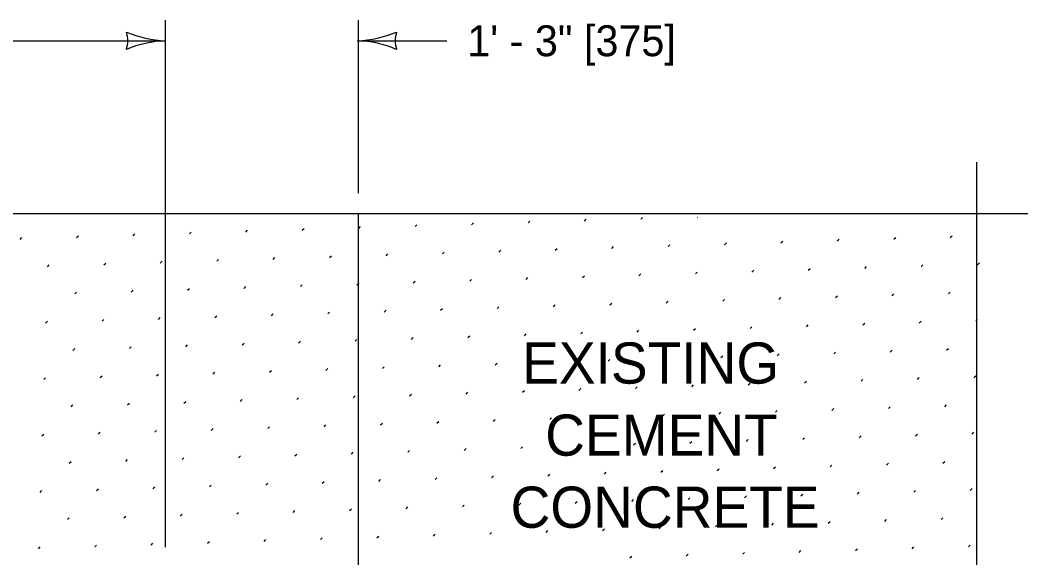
# Model space of a CAD drawing. Extents: x 49991.4 to 50021, y 49987.6 to 50011.4.
# Drawn here: x 50005.45 to 50007.407, y 49992.135 to 49993.18 of the extents above; entities that cross this region are included whole.
import ezdxf

# ---------------------------------------------------------------- set-up
doc = ezdxf.new("R2010")
doc.units = 0
for name, color, linetype in [('Level 1', 7, 'Continuous'), ('Level 10', 7, 'Continuous'), ('Level 2', 7, 'Continuous'), ('Level 3', 7, 'Continuous'), ('Level 6', 7, 'Continuous')]:
    doc.layers.add(name, color=color, linetype=linetype)

msp = doc.modelspace()

# ---------------------------------------------------------------- linework, layer by layer
at = {"layer": 'Level 1'}
msp.add_line((50006.1071, 49991.8039), (50006.1071, 49992.8039), dxfattribs=at)
at = {"layer": 'Level 10'}
for p, q in [((50006.4361, 49992.786), (50006.4396, 49992.7896)), ((50006.5457, 49992.7896), (50006.5492, 49992.7931)), ((50006.6553, 49992.7931), (50006.6588, 49992.7967)), ((50006.7649, 49992.7967), (50006.7656, 49992.7974)), ((50005.7784, 49992.7648), (50005.7819, 49992.7683)), ((50005.888, 49992.7683), (50005.8915, 49992.7719)), ((50005.9976, 49992.7719), (50006.0012, 49992.7754)), ((50006.1072, 49992.7754), (50006.1108, 49992.779)), ((50006.2168, 49992.779), (50006.2204, 49992.7825)), ((50006.3264, 49992.7825), (50006.33, 49992.786)), ((50005.4496, 49992.7542), (50005.4531, 49992.7577)), ((50005.5592, 49992.7577), (50005.5627, 49992.7612)), ((50005.6688, 49992.7612), (50005.6723, 49992.7648)), ((50006.9275, 49992.7472), (50006.9311, 49992.7507)), ((50007.0371, 49992.7507), (50007.0407, 49992.7543)), ((50007.1467, 49992.7543), (50007.1503, 49992.7578)), ((50007.2563, 49992.7578), (50007.2599, 49992.7613)), ((50006.2699, 49992.7259), (50006.2734, 49992.7295)), ((50006.3795, 49992.7295), (50006.383, 49992.733)), ((50006.4891, 49992.733), (50006.4926, 49992.7366)), ((50006.5987, 49992.7366), (50006.6022, 49992.7401)), ((50006.7083, 49992.7401), (50006.7118, 49992.7436)), ((50006.8179, 49992.7436), (50006.8214, 49992.7472)), ((50005.7218, 49992.7082), (50005.7254, 49992.7118)), ((50005.8314, 49992.7118), (50005.835, 49992.7153)), ((50005.941, 49992.7153), (50005.9446, 49992.7188)), ((50006.0507, 49992.7188), (50006.0542, 49992.7224)), ((50006.1603, 49992.7224), (50006.1638, 49992.7259)), ((50005.5026, 49992.7011), (50005.5061, 49992.7047)), ((50005.6122, 49992.7047), (50005.6158, 49992.7082)), ((50006.7613, 49992.6871), (50006.7649, 49992.6906)), ((50006.8709, 49992.6906), (50006.8745, 49992.6941)), ((50006.9806, 49992.6942), (50006.9841, 49992.6977)), ((50007.0902, 49992.6977), (50007.0937, 49992.7012)), ((50007.1998, 49992.7012), (50007.2033, 49992.7048)), ((50007.3094, 49992.7048), (50007.3129, 49992.7083)), ((50006.1037, 49992.6658), (50006.1072, 49992.6693)), ((50006.2133, 49992.6694), (50006.2168, 49992.6729)), ((50006.3229, 49992.6729), (50006.3264, 49992.6764)), ((50006.4325, 49992.6764), (50006.436, 49992.68)), ((50006.5421, 49992.68), (50006.5457, 49992.6835)), ((50006.6517, 49992.6835), (50006.6553, 49992.6871)), ((50005.5556, 49992.6481), (50005.5592, 49992.6516)), ((50005.6652, 49992.6516), (50005.6688, 49992.6552)), ((50005.7749, 49992.6552), (50005.7784, 49992.6587)), ((50005.8845, 49992.6587), (50005.888, 49992.6623)), ((50005.9941, 49992.6623), (50005.9976, 49992.6658)), ((50007.2528, 49992.6482), (50007.2563, 49992.6517)), ((50006.5952, 49992.6269), (50006.5987, 49992.6305)), ((50006.7048, 49992.6305), (50006.7083, 49992.634)), ((50006.8144, 49992.634), (50006.8179, 49992.6376)), ((50006.924, 49992.6376), (50006.9275, 49992.6411)), ((50007.0336, 49992.6411), (50007.0371, 49992.6447)), ((50007.1432, 49992.6447), (50007.1467, 49992.6482)), ((50006.0471, 49992.6092), (50006.0506, 49992.6128)), ((50006.1567, 49992.6128), (50006.1603, 49992.6163)), ((50006.2663, 49992.6163), (50006.2699, 49992.6199)), ((50006.3759, 49992.6199), (50006.3795, 49992.6234)), ((50006.4855, 49992.6234), (50006.4891, 49992.6269)), ((50005.4991, 49992.5915), (50005.5026, 49992.5951)), ((50005.6087, 49992.5951), (50005.6122, 49992.5986)), ((50005.7183, 49992.5986), (50005.7218, 49992.6021)), ((50005.8279, 49992.6022), (50005.8314, 49992.6057)), ((50005.9375, 49992.6057), (50005.941, 49992.6092)), ((50007.0866, 49992.5881), (50007.0902, 49992.5916)), ((50007.1962, 49992.5916), (50007.1998, 49992.5952)), ((50007.3058, 49992.5952), (50007.3094, 49992.5987)), ((50006.5386, 49992.5704), (50006.5421, 49992.5739)), ((50006.6482, 49992.5739), (50006.6517, 49992.5775)), ((50006.7578, 49992.5775), (50006.7613, 49992.581)), ((50006.8674, 49992.581), (50006.8709, 49992.5845)), ((50006.977, 49992.5845), (50006.9805, 49992.5881)), ((50005.8809, 49992.5491), (50005.8845, 49992.5527)), ((50005.9905, 49992.5527), (50005.9941, 49992.5562)), ((50006.1001, 49992.5562), (50006.1037, 49992.5597)), ((50006.2097, 49992.5597), (50006.2133, 49992.5633)), ((50006.3194, 49992.5633), (50006.3229, 49992.5668)), ((50006.429, 49992.5668), (50006.4325, 49992.5704)), ((50005.5521, 49992.5385), (50005.5556, 49992.542)), ((50005.6617, 49992.542), (50005.6652, 49992.5456)), ((50005.7713, 49992.5456), (50005.7749, 49992.5491)), ((50007.03, 49992.5315), (50007.0336, 49992.535)), ((50007.1397, 49992.5351), (50007.1432, 49992.5386)), ((50007.2493, 49992.5386), (50007.2528, 49992.5421)), ((50006.3724, 49992.5103), (50006.3759, 49992.5138)), ((50006.482, 49992.5138), (50006.4855, 49992.5173)), ((50006.5916, 49992.5173), (50006.5951, 49992.5209)), ((50006.7012, 49992.5209), (50006.7048, 49992.5244)), ((50006.8108, 49992.5244), (50006.8144, 49992.528)), ((50006.9204, 49992.528), (50006.924, 49992.5315)), ((50005.8243, 49992.4925), (50005.8279, 49992.4961)), ((50005.934, 49992.4961), (50005.9375, 49992.4996)), ((50006.0436, 49992.4996), (50006.0471, 49992.5032)), ((50006.1532, 49992.5032), (50006.1567, 49992.5067)), ((50006.2628, 49992.5067), (50006.2663, 49992.5102)), ((50005.4955, 49992.4819), (50005.4991, 49992.4854)), ((50005.6051, 49992.4855), (50005.6087, 49992.489)), ((50005.7147, 49992.489), (50005.7183, 49992.4925)), ((50006.8639, 49992.4714), (50006.8674, 49992.4749)), ((50006.9735, 49992.4749), (50006.977, 49992.4785)), ((50007.0831, 49992.4785), (50007.0866, 49992.482)), ((50007.1927, 49992.482), (50007.1962, 49992.4856)), ((50007.3023, 49992.4856), (50007.3058, 49992.4891)), ((50006.3158, 49992.4537), (50006.3194, 49992.4572)), ((50006.4254, 49992.4572), (50006.429, 49992.4608)), ((50006.535, 49992.4608), (50006.5386, 49992.4643)), ((50006.6446, 49992.4643), (50006.6482, 49992.4678)), ((50006.7543, 49992.4678), (50006.7578, 49992.4714)), ((50005.6582, 49992.4324), (50005.6617, 49992.436)), ((50005.7678, 49992.436), (50005.7713, 49992.4395)), ((50005.8774, 49992.4395), (50005.8809, 49992.443)), ((50005.987, 49992.4431), (50005.9905, 49992.4466)), ((50006.0966, 49992.4466), (50006.1001, 49992.4501)), ((50006.2062, 49992.4501), (50006.2097, 49992.4537)), ((50005.5486, 49992.4289), (50005.5521, 49992.4324)), ((50006.8073, 49992.4148), (50006.8108, 49992.4184)), ((50006.9169, 49992.4184), (50006.9204, 49992.4219)), ((50007.0265, 49992.4219), (50007.03, 49992.4254)), ((50007.1361, 49992.4254), (50007.1396, 49992.429)), ((50007.2457, 49992.429), (50007.2493, 49992.4325)), ((50006.1496, 49992.3936), (50006.1532, 49992.3971)), ((50006.2592, 49992.3971), (50006.2628, 49992.4006)), ((50006.3688, 49992.4006), (50006.3724, 49992.4042)), ((50006.4785, 49992.4042), (50006.482, 49992.4077)), ((50006.5881, 49992.4077), (50006.5916, 49992.4113)), ((50006.6977, 49992.4113), (50006.7012, 49992.4148)), ((50005.492, 49992.3723), (50005.4955, 49992.3758)), ((50005.6016, 49992.3758), (50005.6051, 49992.3794)), ((50005.7112, 49992.3794), (50005.7147, 49992.3829)), ((50005.8208, 49992.3829), (50005.8243, 49992.3865)), ((50005.9304, 49992.3865), (50005.9339, 49992.39)), ((50006.04, 49992.39), (50006.0436, 49992.3936)), ((50007.1891, 49992.3724), (50007.1927, 49992.3759)), ((50007.2988, 49992.376), (50007.3023, 49992.3795)), ((50006.6411, 49992.3547), (50006.6446, 49992.3582)), ((50006.7507, 49992.3582), (50006.7542, 49992.3618)), ((50006.8603, 49992.3618), (50006.8639, 49992.3653)), ((50006.9699, 49992.3653), (50006.9735, 49992.3689)), ((50007.0795, 49992.3689), (50007.0831, 49992.3724)), ((50005.9834, 49992.3334), (50005.987, 49992.337)), ((50006.0931, 49992.337), (50006.0966, 49992.3405)), ((50006.2027, 49992.3405), (50006.2062, 49992.3441)), ((50006.3123, 49992.3441), (50006.3158, 49992.3476)), ((50006.4219, 49992.3476), (50006.4254, 49992.3511)), ((50006.5315, 49992.3512), (50006.535, 49992.3547)), ((50005.545, 49992.3193), (50005.5485, 49992.3228)), ((50005.6546, 49992.3228), (50005.6582, 49992.3264)), ((50005.7642, 49992.3264), (50005.7678, 49992.3299)), ((50005.8738, 49992.3299), (50005.8774, 49992.3334)), ((50007.1326, 49992.3158), (50007.1361, 49992.3194)), ((50007.2422, 49992.3194), (50007.2457, 49992.3229)), ((50006.4749, 49992.2946), (50006.4785, 49992.2981)), ((50006.5845, 49992.2981), (50006.5881, 49992.3017)), ((50006.6941, 49992.3017), (50006.6977, 49992.3052)), ((50006.8037, 49992.3052), (50006.8073, 49992.3087)), ((50006.9133, 49992.3088), (50006.9169, 49992.3123)), ((50007.023, 49992.3123), (50007.0265, 49992.3158)), ((50005.9269, 49992.2769), (50005.9304, 49992.2804)), ((50006.0365, 49992.2804), (50006.04, 49992.2839)), ((50006.1461, 49992.284), (50006.1496, 49992.2875)), ((50006.2557, 49992.2875), (50006.2592, 49992.291)), ((50006.3653, 49992.291), (50006.3688, 49992.2946)), ((50005.4884, 49992.2627), (50005.492, 49992.2662)), ((50005.598, 49992.2662), (50005.6016, 49992.2698)), ((50005.7077, 49992.2698), (50005.7112, 49992.2733)), ((50005.8173, 49992.2733), (50005.8208, 49992.2769)), ((50006.9664, 49992.2557), (50006.9699, 49992.2593)), ((50007.076, 49992.2593), (50007.0795, 49992.2628)), ((50007.1856, 49992.2628), (50007.1891, 49992.2663)), ((50007.2952, 49992.2663), (50007.2987, 49992.2699)), ((50006.4183, 49992.238), (50006.4219, 49992.2415)), ((50006.5279, 49992.2415), (50006.5315, 49992.2451)), ((50006.6376, 49992.2451), (50006.6411, 49992.2486)), ((50006.7472, 49992.2486), (50006.7507, 49992.2522)), ((50006.8568, 49992.2522), (50006.8603, 49992.2557)), ((50005.7607, 49992.2167), (50005.7642, 49992.2203)), ((50005.8703, 49992.2203), (50005.8738, 49992.2238)), ((50005.9799, 49992.2238), (50005.9834, 49992.2274)), ((50006.0895, 49992.2274), (50006.093, 49992.2309)), ((50006.1991, 49992.2309), (50006.2027, 49992.2345)), ((50006.3087, 49992.2345), (50006.3123, 49992.238)), ((50005.5415, 49992.2097), (50005.545, 49992.2132)), ((50005.6511, 49992.2132), (50005.6546, 49992.2167)), ((50006.9098, 49992.1991), (50006.9133, 49992.2027)), ((50007.0194, 49992.2027), (50007.023, 49992.2062)), ((50007.129, 49992.2062), (50007.1326, 49992.2098)), ((50007.2386, 49992.2098), (50007.2422, 49992.2133)), ((50006.2522, 49992.1779), (50006.2557, 49992.1814)), ((50006.3618, 49992.1814), (50006.3653, 49992.185)), ((50006.4714, 49992.185), (50006.4749, 49992.1885)), ((50006.581, 49992.1885), (50006.5845, 49992.192)), ((50006.6906, 49992.1921), (50006.6941, 49992.1956)), ((50006.8002, 49992.1956), (50006.8037, 49992.1991)), ((50005.7041, 49992.1602), (50005.7076, 49992.1637)), ((50005.8137, 49992.1637), (50005.8173, 49992.1673)), ((50005.9233, 49992.1673), (50005.9269, 49992.1708)), ((50006.0329, 49992.1708), (50006.0365, 49992.1743)), ((50006.1425, 49992.1743), (50006.1461, 49992.1779)), ((50005.4849, 49992.1531), (50005.4884, 49992.1566)), ((50005.5945, 49992.1566), (50005.598, 49992.1602)), ((50006.7436, 49992.139), (50006.7472, 49992.1426)), ((50006.8532, 49992.1426), (50006.8568, 49992.1461)), ((50006.9628, 49992.1461), (50006.9664, 49992.1496)), ((50007.0724, 49992.1497), (50007.076, 49992.1532)), ((50007.1821, 49992.1532), (50007.1856, 49992.1567)), ((50007.2917, 49992.1567), (50007.2952, 49992.1603)), ((50006.634, 49992.1355), (50006.6375, 49992.139))]:
    msp.add_line(p, q, dxfattribs=at)
at = {"layer": 'Level 3'}
for p, q in [((50005.7321, 49992.1564), (50005.7321, 49993.18)), ((50006.1071, 49992.8439), (50006.1071, 49993.18)), ((50002.7321, 49993.14), (50005.7321, 49993.14)), ((50006.1071, 49993.14), (50006.2782, 49993.14))]:
    msp.add_line(p, q, dxfattribs=at)
for centre, radius, start, end in [((50005.7412, 49993.3621), 0.2223, 247.4572, 267.6407), ((50005.6038, 49993.14), 0.0548, 342.14, 17.8624), ((50005.7436, 49992.9073), 0.233, 92.8285, 112.0784), ((50006.0933, 49993.3728), 0.233, 272.8285, 292.0784), ((50006.0956, 49992.918), 0.2223, 67.4572, 87.6407), ((50006.233, 49993.1401), 0.0548, 162.14, 197.8624)]:
    msp.add_arc(centre, radius, start, end, dxfattribs=at)
at = {"layer": 'Level 6'}
for p, q in [((50007.3071, 49992.9039), (50007.3071, 49991.6187)), ((50007.4071, 49992.8039), (50005.3219, 49992.8039))]:
    msp.add_line(p, q, dxfattribs=at)

# ---------------------------------------------------------------- texts
at = {"layer": 'Level 2'}
for s, height, p in [('1\' - 3" [375]', 0.06, (50006.3182, 49993.11)), ('EXISTING', 0.08, (50006.4247, 49992.4739)), ('CEMENT', 0.08, (50006.4695, 49992.3339)), ('CONCRETE', 0.08, (50006.4022, 49992.1939))]:
    msp.add_text(s, height=height, dxfattribs=at).set_placement(p)

doc.saveas('drawing.dxf')
